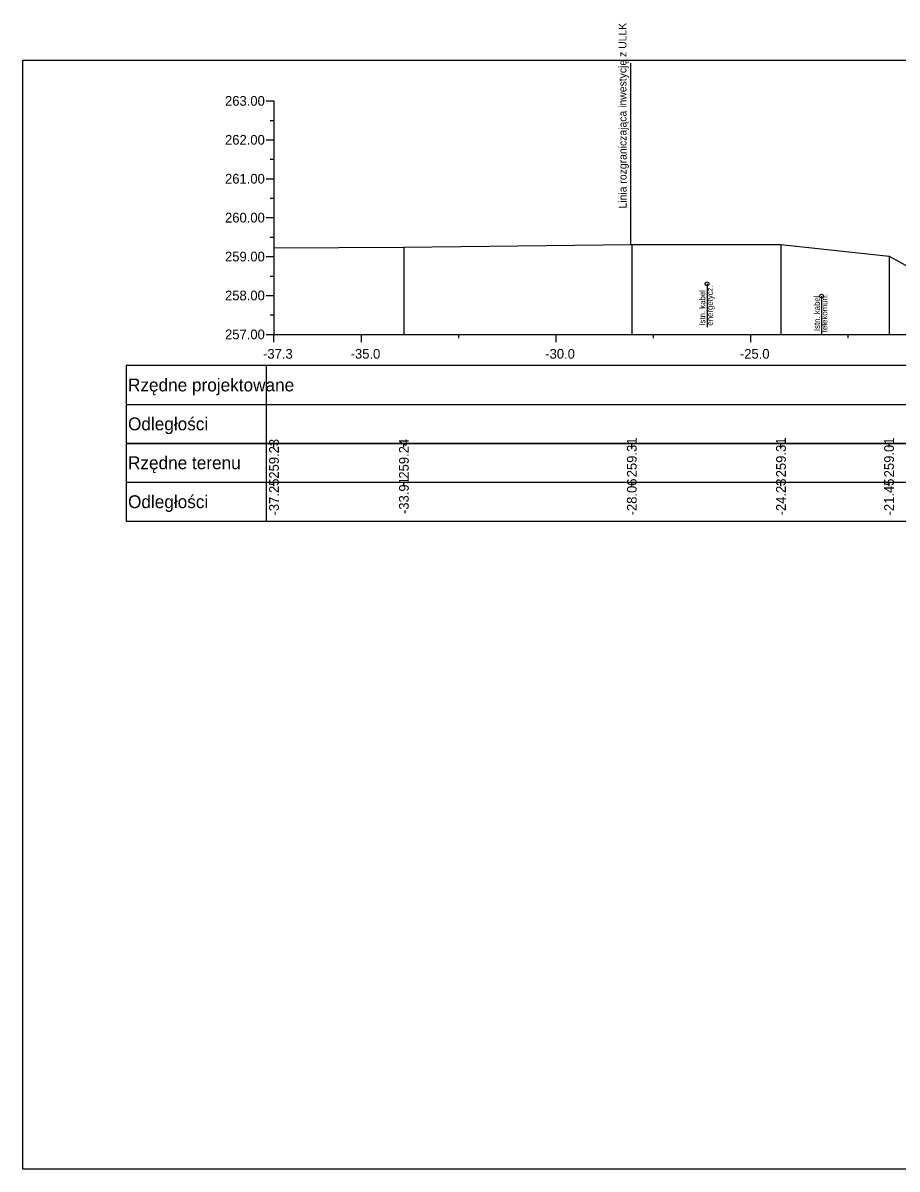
# Model space of a CAD drawing. Extents: x 6516023 to 6560129, y 5513077 to 5529206.
# Drawn here: x 6517179.51 to 6517201.97, y 5514484.66 to 5514514.11 of the extents above; entities that cross this region are included whole.
import ezdxf

# ---------------------------------------------------------------- set-up
doc = ezdxf.new("R2010")
doc.units = 0
for name, color, linetype in [('TOR_PRZEK_P-kable', 7, 'Continuous'), ('TOR_PRZEK_P-tabelka istniejace', 7, 'Continuous'), ('TOR_PRZEK_P-tabelka projektowane', 7, 'Continuous'), ('TOR_PRZEK_P-teren istniejacy', 7, 'Continuous'), ('TOR_PRZEK_P-uklad odniesienia', 7, 'Continuous'), ('TOR_PS_T-granica PKP-projektowana', 7, 'Continuous'), ('TOR_RAMKI-ramka+tabelka 1', 7, 'Continuous')]:
    doc.layers.add(name, color=color, linetype=linetype)

msp = doc.modelspace()

# ---------------------------------------------------------------- linework, layer by layer
at = {"layer": 'TOR_PRZEK_P-kable'}
for p, q in [((6517197.089, 5514507.404), (6517197.089, 5514506.294)), ((6517200.032, 5514507.088), (6517200.032, 5514506.114))]:
    msp.add_line(p, q, dxfattribs=at)
for centre in [(6517197.089, 5514507.404), (6517200.032, 5514507.088)]:
    msp.add_circle(centre, 0.05, dxfattribs=at)
at = {"layer": 'TOR_PRZEK_P-tabelka istniejace'}
for p, q in [((6517182.163, 5514503.306), (6517182.163, 5514501.306)), ((6517185.763, 5514503.306), (6517185.763, 5514501.306)), ((6517185.963, 5514503.206), (6517185.963, 5514503.306)), ((6517189.3, 5514503.206), (6517189.3, 5514503.306)), ((6517195.156, 5514503.206), (6517195.156, 5514503.306)), ((6517198.988, 5514503.206), (6517198.988, 5514503.306)), ((6517201.764, 5514503.206), (6517201.764, 5514503.306)), ((6517182.163, 5514502.306), (6517265.963, 5514502.306)), ((6517185.963, 5514502.206), (6517185.963, 5514502.306)), ((6517189.3, 5514502.206), (6517189.3, 5514502.306)), ((6517195.156, 5514502.206), (6517195.156, 5514502.306)), ((6517198.988, 5514502.206), (6517198.988, 5514502.306)), ((6517201.764, 5514502.206), (6517201.764, 5514502.306))]:
    msp.add_line(p, q, dxfattribs=at)
for points in [[(6517185.963, 5514508.334), (6517185.963, 5514506.306), (6517185.963, 5514506.176), (6517185.963, 5514506.106)], [(6517189.3, 5514508.35), (6517189.3, 5514506.306), (6517189.3, 5514506.176), (6517189.3, 5514506.106)], [(6517195.156, 5514508.42), (6517195.156, 5514506.306), (6517195.156, 5514506.176), (6517195.156, 5514506.106)], [(6517198.988, 5514508.419), (6517198.988, 5514506.306), (6517198.988, 5514506.176), (6517198.988, 5514506.106)], [(6517201.764, 5514508.119), (6517201.764, 5514506.306), (6517201.764, 5514506.176), (6517201.764, 5514506.106)]]:
    msp.add_lwpolyline(points, dxfattribs=at)
msp.add_lwpolyline([(6517182.163, 5514503.306), (6517182.163, 5514501.306), (6517265.963, 5514501.306), (6517265.963, 5514503.306)], close=True, dxfattribs=at)
at = {"layer": 'TOR_PRZEK_P-tabelka projektowane'}
for p, q in [((6517182.163, 5514505.306), (6517182.163, 5514503.306)), ((6517185.763, 5514505.306), (6517185.763, 5514503.306)), ((6517182.163, 5514504.306), (6517265.963, 5514504.306))]:
    msp.add_line(p, q, dxfattribs=at)
msp.add_lwpolyline([(6517182.163, 5514505.306), (6517182.163, 5514503.306), (6517265.963, 5514503.306), (6517265.963, 5514505.306)], close=True, dxfattribs=at)
at = {"layer": 'TOR_PRZEK_P-teren istniejacy'}
msp.add_lwpolyline([(6517185.963, 5514508.334), (6517189.3, 5514508.35), (6517195.156, 5514508.42), (6517198.988, 5514508.419), (6517201.764, 5514508.119), (6517202.671, 5514507.618)], dxfattribs=at)
at = {"layer": 'TOR_PRZEK_P-uklad odniesienia'}
for p, q in [((6517185.763, 5514512.106), (6517185.963, 5514512.106)), ((6517185.963, 5514512.106), (6517185.963, 5514506.106)), ((6517185.863, 5514511.606), (6517185.963, 5514511.606)), ((6517185.763, 5514511.106), (6517185.963, 5514511.106)), ((6517185.863, 5514510.606), (6517185.963, 5514510.606)), ((6517185.763, 5514510.106), (6517185.963, 5514510.106)), ((6517185.863, 5514509.606), (6517185.963, 5514509.606)), ((6517185.763, 5514509.106), (6517185.963, 5514509.106)), ((6517185.863, 5514508.606), (6517185.963, 5514508.606)), ((6517185.763, 5514508.106), (6517185.963, 5514508.106)), ((6517185.863, 5514507.606), (6517185.963, 5514507.606)), ((6517185.763, 5514507.106), (6517185.963, 5514507.106)), ((6517185.863, 5514506.606), (6517185.963, 5514506.606)), ((6517185.763, 5514506.106), (6517185.963, 5514506.106)), ((6517185.963, 5514506.106), (6517265.963, 5514506.106)), ((6517185.963, 5514506.006), (6517185.963, 5514506.106)), ((6517185.963, 5514505.906), (6517185.963, 5514506.106)), ((6517188.213, 5514505.906), (6517188.213, 5514506.106)), ((6517190.713, 5514506.006), (6517190.713, 5514506.106)), ((6517193.213, 5514505.906), (6517193.213, 5514506.106)), ((6517195.713, 5514506.006), (6517195.713, 5514506.106)), ((6517198.213, 5514505.906), (6517198.213, 5514506.106)), ((6517200.713, 5514506.006), (6517200.713, 5514506.106))]:
    msp.add_line(p, q, dxfattribs=at)
at = {"layer": 'TOR_PS_T-granica PKP-projektowana'}
msp.add_line((6517195.131, 5514508.419), (6517195.131, 5514513.077), dxfattribs=at)
at = {"layer": 'TOR_RAMKI-ramka+tabelka 1'}
msp.add_lwpolyline([(6517179.513, 5514513.156), (6517427.013, 5514513.156), (6517427.013, 5514484.656), (6517179.513, 5514484.656)], close=True, dxfattribs=at)

# ---------------------------------------------------------------- texts
at = {"layer": 'TOR_PRZEK_P-kable'}
for s, height, p in [('energetycz.', 0.14999, (6517197.238, 5514506.331)), ('Istn. kabel', 0.14999, (6517197.044, 5514506.331)), ('Istn. kabel', 0.14999, (6517199.987, 5514506.19)), ('telekomun.', 0.15, (6517200.181, 5514506.162))]:
    msp.add_text(s, height=height, rotation=90.0511, dxfattribs=at).set_placement(p)
at = {"layer": 'TOR_PRZEK_P-tabelka istniejace'}
for s, p in [('259.23', (6517186.088, 5514502.398)), ('259.24', (6517189.425, 5514502.399)), ('259.31', (6517195.281, 5514502.433)), ('259.31', (6517199.113, 5514502.433)), ('259.01', (6517201.889, 5514502.433)), ('-37.25', (6517186.088, 5514501.453)), ('-33.91', (6517189.425, 5514501.489)), ('-28.06', (6517195.281, 5514501.454)), ('-24.23', (6517199.113, 5514501.454)), ('-21.45', (6517201.889, 5514501.453))]:
    msp.add_text(s, height=0.25, rotation=90, dxfattribs=at).set_placement(p)
for s, p in [('Rzędne terenu', (6517182.213, 5514502.641)), ('Odległości', (6517182.213, 5514501.641))]:
    msp.add_text(s, height=0.33, dxfattribs=at).set_placement(p)
at = {"layer": 'TOR_PRZEK_P-tabelka projektowane'}
for s, p in [('Rzędne projektowane', (6517182.213, 5514504.641)), ('Odległości', (6517182.213, 5514503.641))]:
    msp.add_text(s, height=0.33, dxfattribs=at).set_placement(p)
at = {"layer": 'TOR_PRZEK_P-uklad odniesienia'}
for s, height, p in [('263.00', 0.25, (6517184.705, 5514511.981)), ('262.00', 0.25, (6517184.705, 5514510.981)), ('261.00', 0.25, (6517184.705, 5514509.981)), ('260.00', 0.25, (6517184.705, 5514508.981)), ('259.00', 0.25, (6517184.705, 5514507.981)), ('258.00', 0.25, (6517184.705, 5514506.981)), ('257.00', 0.25, (6517184.705, 5514505.981)), ('-', 0.0001, (6517185.963, 5514506.106)), ('-37.3', 0.25, (6517185.682, 5514505.481)), ('-35.0', 0.25, (6517187.932, 5514505.481)), ('-30.0', 0.25, (6517192.932, 5514505.481)), ('-25.0', 0.25, (6517197.932, 5514505.481))]:
    msp.add_text(s, height=height, dxfattribs=at).set_placement(p)
at = {"layer": 'TOR_PS_T-granica PKP-projektowana'}
msp.add_text('Linia rozgraniczająca inwestycję z ULLK', height=0.2, rotation=90.0511, dxfattribs=at).set_placement((6517195.021, 5514509.341))

doc.saveas('drawing.dxf')
